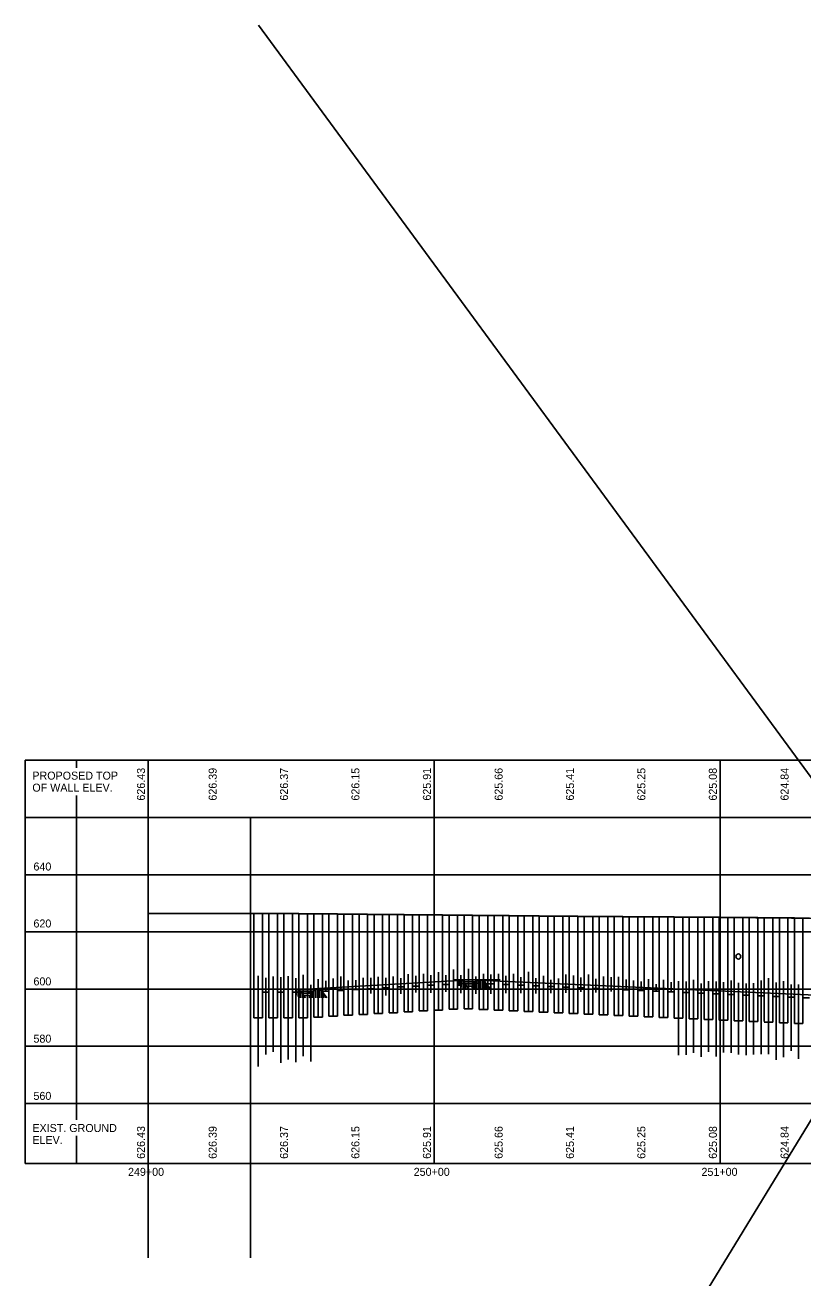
# Model space of a CAD drawing. Extents: x 2267596 to 2268160, y 712626 to 714793.
# Drawn here: x 2267595.7 to 2267867.7, y 712887.4 to 713325.6 of the extents above; entities that cross this region are included whole.
import ezdxf

# ---------------------------------------------------------------- set-up
doc = ezdxf.new("R2010")
doc.units = 0
for name, color, linetype in [('BR_P_Gen_Text', 7, 'Continuous'), ('BR_P_Sub_Deep_Object', 7, 'Continuous'), ('Default', 7, 'Continuous'), ('DR_X_Storm_Sewer', 7, 'Continuous'), ('GE_X_Alignment', 7, 'Continuous'), ('SC_Scratch1', 7, 'Continuous'), ('SC_Scratch9', 7, 'Continuous'), ('SH_Major_Grid_Line', 7, 'Continuous'), ('XS_X_Ground_Line', 7, 'Continuous')]:
    doc.layers.add(name, color=color, linetype=linetype)

msp = doc.modelspace()

# ---------------------------------------------------------------- linework, layer by layer
at = {"layer": 'BR_P_Sub_Deep_Object'}
for p, q in [((2267675.74, 713014.81), (2267675.74, 712978.33)), ((2267675.74, 713014.81), (2267678.74, 713014.81)), ((2267678.74, 713014.81), (2267678.74, 712978.33)), ((2267678.74, 713014.81), (2267680.99, 713014.81)), ((2267680.99, 713014.81), (2267680.99, 712978.33)), ((2267680.99, 713014.81), (2267683.99, 713014.8)), ((2267683.99, 713014.8), (2267683.99, 712978.33)), ((2267683.99, 713014.8), (2267686.24, 713014.8)), ((2267686.24, 713014.8), (2267686.24, 712978.33)), ((2267686.24, 713014.8), (2267689.24, 713014.8)), ((2267689.24, 713014.8), (2267689.24, 712978.33)), ((2267689.24, 713014.8), (2267691.49, 713014.8)), ((2267691.49, 713014.8), (2267691.49, 712978.34)), ((2267691.49, 713014.78), (2267694.49, 713014.78)), ((2267694.49, 713014.78), (2267694.49, 712978.34)), ((2267694.49, 713014.75), (2267696.74, 713014.75)), ((2267696.74, 713014.75), (2267696.74, 712978.64)), ((2267696.74, 713014.73), (2267699.74, 713014.73)), ((2267699.74, 713014.73), (2267699.74, 712978.64)), ((2267699.74, 713014.7), (2267701.99, 713014.7)), ((2267701.99, 713014.7), (2267701.99, 712978.94)), ((2267701.99, 713014.68), (2267704.99, 713014.68)), ((2267704.99, 713014.68), (2267704.99, 712978.94)), ((2267704.99, 713014.66), (2267707.24, 713014.66)), ((2267707.24, 713014.66), (2267707.24, 712979.25)), ((2267707.24, 713014.64), (2267710.24, 713014.64)), ((2267710.24, 713014.64), (2267710.24, 712979.25)), ((2267710.24, 713014.61), (2267712.49, 713014.61)), ((2267712.49, 713014.61), (2267712.49, 712979.55)), ((2267712.49, 713014.59), (2267715.49, 713014.59)), ((2267715.49, 713014.59), (2267715.49, 712979.55)), ((2267715.49, 713014.56), (2267717.74, 713014.56)), ((2267717.74, 713014.56), (2267717.74, 712979.86)), ((2267717.74, 713014.54), (2267720.74, 713014.54)), ((2267720.74, 713014.54), (2267720.74, 712979.86)), ((2267720.74, 713014.51), (2267722.99, 713014.51)), ((2267722.99, 713014.51), (2267722.99, 712980.16)), ((2267722.99, 713014.49), (2267725.99, 713014.49)), ((2267725.99, 713014.49), (2267725.99, 712980.16)), ((2267725.99, 713014.46), (2267728.24, 713014.46)), ((2267728.24, 713014.46), (2267728.24, 712980.47)), ((2267728.24, 713014.44), (2267731.24, 713014.44)), ((2267731.24, 713014.44), (2267731.24, 712980.47)), ((2267731.24, 713014.41), (2267733.49, 713014.41)), ((2267733.49, 713014.41), (2267733.49, 712980.77)), ((2267733.49, 713014.39), (2267736.49, 713014.39)), ((2267736.49, 713014.39), (2267736.49, 712980.77)), ((2267736.49, 713014.36), (2267738.74, 713014.36)), ((2267738.74, 712981.07), (2267738.74, 713014.36)), ((2267738.74, 713014.34), (2267741.74, 713014.34)), ((2267741.74, 713014.34), (2267741.74, 712981.07)), ((2267741.74, 713014.31), (2267743.99, 713014.31)), ((2267743.99, 713014.31), (2267743.99, 712981.38)), ((2267743.99, 713014.29), (2267746.99, 713014.29)), ((2267746.99, 713014.29), (2267746.99, 712981.38)), ((2267746.99, 713014.26), (2267749.24, 713014.26)), ((2267749.24, 713014.26), (2267749.24, 712981.49)), ((2267749.24, 713014.23), (2267752.24, 713014.23)), ((2267752.24, 713014.23), (2267752.24, 712981.49)), ((2267752.24, 713014.2), (2267754.49, 713014.2)), ((2267754.49, 713014.2), (2267754.49, 712981.25)), ((2267754.49, 713014.18), (2267757.49, 713014.18)), ((2267757.49, 713014.18), (2267757.49, 712981.25)), ((2267757.49, 713014.15), (2267759.74, 713014.15)), ((2267759.74, 713014.15), (2267759.74, 712981.02)), ((2267759.74, 713014.13), (2267762.74, 713014.13)), ((2267762.74, 713014.13), (2267762.74, 712981.02)), ((2267762.74, 713014.1), (2267764.99, 713014.1)), ((2267764.99, 713014.1), (2267764.99, 712980.79)), ((2267764.99, 713014.08), (2267767.99, 713014.08)), ((2267767.99, 713014.08), (2267767.99, 712980.79)), ((2267767.99, 713014.05), (2267770.24, 713014.05)), ((2267770.24, 713014.05), (2267770.24, 712980.55)), ((2267770.24, 713014.02), (2267773.24, 713014.02)), ((2267773.24, 713014.02), (2267773.24, 712980.55)), ((2267773.24, 713013.99), (2267775.49, 713013.99)), ((2267775.49, 713013.99), (2267775.49, 712980.32)), ((2267775.49, 713013.97), (2267778.49, 713013.97)), ((2267778.49, 713013.97), (2267778.49, 712980.32)), ((2267778.49, 713013.94), (2267780.74, 713013.94)), ((2267780.74, 713013.94), (2267780.74, 712980.08)), ((2267780.74, 713013.92), (2267783.74, 713013.92)), ((2267783.74, 713013.92), (2267783.74, 712980.08)), ((2267783.74, 713013.89), (2267785.99, 713013.89)), ((2267785.99, 713013.89), (2267785.99, 712979.85)), ((2267785.99, 713013.87), (2267788.99, 713013.87)), ((2267788.99, 713013.87), (2267788.99, 712979.85)), ((2267788.99, 713013.84), (2267791.24, 713013.84)), ((2267791.24, 713013.84), (2267791.24, 712979.62)), ((2267791.24, 713013.82), (2267794.24, 713013.82)), ((2267794.24, 713013.82), (2267794.24, 712979.62)), ((2267794.24, 713013.8), (2267796.49, 713013.8)), ((2267796.49, 713013.8), (2267796.49, 712979.38)), ((2267796.49, 713013.79), (2267799.49, 713013.79)), ((2267799.49, 713013.79), (2267799.49, 712979.38)), ((2267799.49, 713013.77), (2267801.74, 713013.77)), ((2267801.74, 713013.77), (2267801.74, 712979.15)), ((2267801.74, 713013.76), (2267804.74, 713013.76)), ((2267804.74, 713013.76), (2267804.74, 712979.15)), ((2267804.74, 713013.74), (2267806.99, 713013.74)), ((2267806.99, 713013.74), (2267806.99, 712978.91)), ((2267806.99, 713013.72), (2267809.99, 713013.72)), ((2267809.99, 713013.72), (2267809.99, 712978.91)), ((2267809.99, 713013.7), (2267812.24, 713013.7)), ((2267812.24, 713013.7), (2267812.24, 712978.68)), ((2267812.24, 713013.69), (2267815.24, 713013.69)), ((2267815.24, 713013.69), (2267815.24, 712978.68)), ((2267815.24, 713013.67), (2267817.49, 713013.67)), ((2267817.49, 713013.67), (2267817.49, 712978.45)), ((2267817.49, 713013.65), (2267820.49, 713013.65)), ((2267820.49, 713013.65), (2267820.49, 712978.45)), ((2267820.49, 713013.63), (2267822.74, 713013.63)), ((2267822.74, 713013.63), (2267822.74, 712978.21)), ((2267822.74, 713013.62), (2267825.74, 713013.62)), ((2267825.74, 713013.62), (2267825.74, 712978.21)), ((2267825.74, 713013.6), (2267827.99, 713013.6)), ((2267827.99, 713013.6), (2267827.99, 712977.98)), ((2267827.99, 713013.58), (2267830.99, 713013.58)), ((2267830.99, 713013.58), (2267830.99, 712977.98)), ((2267830.99, 713013.56), (2267833.24, 713013.56)), ((2267833.24, 713013.56), (2267833.24, 712977.75)), ((2267833.24, 713013.55), (2267836.24, 713013.55)), ((2267836.24, 713013.55), (2267836.24, 712977.75)), ((2267836.24, 713013.53), (2267838.49, 713013.53)), ((2267838.49, 713013.53), (2267838.49, 712977.51)), ((2267838.49, 713013.51), (2267841.49, 713013.51)), ((2267841.49, 713013.51), (2267841.49, 712977.51)), ((2267841.49, 713013.48), (2267843.74, 713013.48)), ((2267843.74, 713013.48), (2267843.74, 712977.28)), ((2267843.74, 713013.46), (2267846.74, 713013.46)), ((2267846.74, 713013.46), (2267846.74, 712977.28)), ((2267846.74, 713013.43), (2267848.99, 713013.43)), ((2267848.99, 713013.43), (2267848.99, 712977.04)), ((2267848.99, 713013.41), (2267851.99, 713013.41)), ((2267851.99, 713013.41), (2267851.99, 712977.04)), ((2267851.99, 713013.38), (2267854.24, 713013.38)), ((2267854.24, 713013.38), (2267854.24, 712977.04)), ((2267854.24, 713013.36), (2267857.24, 713013.36)), ((2267857.24, 713013.36), (2267857.24, 712976.81)), ((2267857.24, 713013.33), (2267859.49, 713013.33)), ((2267859.49, 713013.33), (2267859.49, 712976.58)), ((2267859.49, 713013.31), (2267862.49, 713013.31)), ((2267862.49, 713013.31), (2267862.49, 712976.58)), ((2267862.49, 713013.28), (2267864.74, 713013.28)), ((2267864.74, 713013.28), (2267864.74, 712976.34)), ((2267864.74, 713013.26), (2267867.74, 713013.26)), ((2267867.74, 713013.26), (2267867.74, 712976.34)), ((2267867.74, 713013.25), (2267869.99, 713013.25)), ((2267731.24, 712989.47), (2267733.49, 712989.47)), ((2267736.49, 712989.77), (2267738.74, 712989.77)), ((2267741.74, 712990.07), (2267743.99, 712990.07)), ((2267746.99, 712990.38), (2267749.24, 712990.38)), ((2267754.49, 712990.49), (2267752.24, 712990.49)), ((2267759.74, 712990.25), (2267757.49, 712990.25)), ((2267764.99, 712990.02), (2267762.74, 712990.02)), ((2267770.24, 712989.79), (2267767.99, 712989.79)), ((2267775.49, 712989.55), (2267773.24, 712989.55)), ((2267780.74, 712989.32), (2267778.49, 712989.32)), ((2267678.74, 712987.33), (2267680.99, 712987.33)), ((2267683.99, 712987.33), (2267686.24, 712987.33)), ((2267689.24, 712987.33), (2267691.49, 712987.33)), ((2267694.49, 712987.34), (2267696.74, 712987.34)), ((2267699.74, 712987.64), (2267701.99, 712987.64)), ((2267704.99, 712987.94), (2267707.24, 712987.94)), ((2267710.24, 712988.25), (2267712.49, 712988.25)), ((2267715.49, 712988.55), (2267717.74, 712988.55)), ((2267720.74, 712988.86), (2267722.99, 712988.86)), ((2267725.99, 712989.16), (2267728.24, 712989.16)), ((2267785.99, 712989.08), (2267783.74, 712989.08)), ((2267791.24, 712988.85), (2267788.99, 712988.85)), ((2267796.49, 712988.62), (2267794.24, 712988.62)), ((2267801.74, 712988.38), (2267799.49, 712988.38)), ((2267806.99, 712988.15), (2267804.74, 712988.15)), ((2267812.24, 712987.91), (2267809.99, 712987.91)), ((2267817.49, 712987.68), (2267815.24, 712987.68)), ((2267822.74, 712987.45), (2267820.49, 712987.45)), ((2267827.99, 712987.21), (2267825.74, 712987.21)), ((2267833.24, 712986.98), (2267830.99, 712986.98)), ((2267838.49, 712986.75), (2267836.24, 712986.75)), ((2267843.74, 712986.51), (2267841.49, 712986.51)), ((2267848.99, 712986.28), (2267846.74, 712986.28)), ((2267854.24, 712986.04), (2267851.99, 712986.04)), ((2267859.49, 712985.81), (2267857.24, 712985.81)), ((2267864.74, 712985.58), (2267862.49, 712985.58)), ((2267869.99, 712985.34), (2267867.74, 712985.34)), ((2267733.49, 712980.77), (2267736.49, 712980.77)), ((2267738.74, 712981.07), (2267741.74, 712981.07)), ((2267743.99, 712981.38), (2267746.99, 712981.38)), ((2267752.24, 712981.49), (2267749.24, 712981.49)), ((2267757.49, 712981.25), (2267754.49, 712981.25)), ((2267762.74, 712981.02), (2267759.74, 712981.02)), ((2267767.99, 712980.79), (2267764.99, 712980.79)), ((2267773.24, 712980.55), (2267770.24, 712980.55)), ((2267675.74, 712978.33), (2267678.74, 712978.33)), ((2267680.99, 712978.33), (2267683.99, 712978.33)), ((2267686.24, 712978.33), (2267689.24, 712978.33)), ((2267691.49, 712978.34), (2267694.49, 712978.34)), ((2267696.74, 712978.64), (2267699.74, 712978.64)), ((2267701.99, 712978.94), (2267704.99, 712978.94)), ((2267707.24, 712979.25), (2267710.24, 712979.25)), ((2267712.49, 712979.55), (2267715.49, 712979.55)), ((2267717.74, 712979.86), (2267720.74, 712979.86)), ((2267722.99, 712980.16), (2267725.99, 712980.16)), ((2267728.24, 712980.47), (2267731.24, 712980.47)), ((2267778.49, 712980.32), (2267775.49, 712980.32)), ((2267783.74, 712980.08), (2267780.74, 712980.08)), ((2267788.99, 712979.85), (2267785.99, 712979.85)), ((2267794.24, 712979.62), (2267791.24, 712979.62)), ((2267799.49, 712979.38), (2267796.49, 712979.38)), ((2267804.74, 712979.15), (2267801.74, 712979.15)), ((2267809.99, 712978.91), (2267806.99, 712978.91)), ((2267815.24, 712978.68), (2267812.24, 712978.68)), ((2267820.49, 712978.45), (2267817.49, 712978.45)), ((2267825.74, 712978.21), (2267822.74, 712978.21)), ((2267830.99, 712977.98), (2267827.99, 712977.98)), ((2267836.24, 712977.75), (2267833.24, 712977.75)), ((2267841.49, 712977.51), (2267838.49, 712977.51)), ((2267846.74, 712977.28), (2267843.74, 712977.28)), ((2267851.99, 712977.04), (2267848.99, 712977.04)), ((2267857.24, 712976.81), (2267854.24, 712976.81)), ((2267862.49, 712976.58), (2267859.49, 712976.58)), ((2267867.74, 712976.34), (2267864.74, 712976.34))]:
    msp.add_line(p, q, dxfattribs=at)
at = {"layer": 'Default'}
for p, q in [((2267761.9, 712991.63), (2267745.5, 712991.63)), ((2267747.52, 712991.63), (2267747.52, 712989.57)), ((2267748.21, 712991.63), (2267748.21, 712989.14)), ((2267748.43, 712991.63), (2267750.7, 712988.68)), ((2267748.9, 712991.02), (2267748.9, 712988.68)), ((2267753.67, 712990.99), (2267748.9, 712990.99)), ((2267753.12, 712990.23), (2267749.51, 712990.23)), ((2267749.59, 712990.12), (2267749.59, 712988.68)), ((2267752.55, 712989.44), (2267750.11, 712989.44)), ((2267754.14, 712991.63), (2267752, 712988.68)), ((2267753.02, 712990.09), (2267753.02, 712988.68)), ((2267753.67, 712990.99), (2267753.67, 712988.68)), ((2267754.36, 712991.63), (2267754.36, 712988.68)), ((2267755.05, 712991.63), (2267755.05, 712988.68)), ((2267755.75, 712991.63), (2267755.75, 712988.68)), ((2267755.96, 712991.63), (2267758.24, 712988.68)), ((2267756.44, 712991.02), (2267756.44, 712988.68)), ((2267757.13, 712990.12), (2267757.13, 712988.68)), ((2267704.94, 712988.33), (2267688.55, 712988.33)), ((2267690.56, 712988.33), (2267690.56, 712986.27)), ((2267691.26, 712988.33), (2267691.26, 712985.84)), ((2267691.47, 712988.33), (2267693.75, 712985.38)), ((2267691.95, 712987.72), (2267691.95, 712985.38)), ((2267696.72, 712987.69), (2267691.95, 712987.69)), ((2267696.17, 712986.93), (2267692.55, 712986.93)), ((2267692.64, 712986.82), (2267692.64, 712985.38)), ((2267695.6, 712986.14), (2267693.16, 712986.14)), ((2267693.32, 712985.93), (2267693.32, 712985.38)), ((2267697.18, 712988.33), (2267695.05, 712985.38)), ((2267695.41, 712985.88), (2267695.41, 712985.38)), ((2267696.07, 712986.79), (2267696.07, 712985.38)), ((2267696.72, 712987.69), (2267696.72, 712985.38)), ((2267697.41, 712988.33), (2267697.41, 712985.38)), ((2267698.1, 712988.33), (2267698.1, 712985.38)), ((2267698.79, 712988.33), (2267698.79, 712985.38)), ((2267699.01, 712988.33), (2267701.29, 712985.38)), ((2267699.48, 712987.72), (2267699.48, 712985.38)), ((2267700.17, 712986.82), (2267700.17, 712985.38)), ((2267700.86, 712985.93), (2267700.86, 712985.38)), ((2267750.27, 712989.23), (2267750.27, 712988.68)), ((2267752.37, 712989.18), (2267752.37, 712988.68)), ((2267757.81, 712989.23), (2267757.81, 712988.68))]:
    msp.add_line(p, q, dxfattribs=at)
at = {"layer": 'DR_X_Storm_Sewer'}
msp.add_circle((2267845.16, 712999.81), 0.876, dxfattribs=at)
at = {"layer": 'GE_X_Alignment'}
for p, q in [((2267613.74, 713065.77), (2267613.74, 713068.43)), ((2267638.74, 712927.44), (2267638.74, 713068.43)), ((2267738.74, 712927.44), (2267738.74, 713068.43)), ((2267838.74, 712927.44), (2267838.74, 713068.43)), ((2267613.74, 712942.64), (2267613.74, 713056.13)), ((2267595.7, 713048.43), (2268156.77, 713048.43)), ((2267595.7, 713028.43), (2268156.77, 713028.43)), ((2267595.7, 713008.43), (2268156.77, 713008.43)), ((2267595.7, 712988.43), (2268156.77, 712988.43)), ((2267595.7, 712968.43), (2268156.77, 712968.43)), ((2267595.7, 712948.43), (2268156.77, 712948.43)), ((2267613.74, 712927.44), (2267613.74, 712937.13))]:
    msp.add_line(p, q, dxfattribs=at)
at = {"layer": 'SC_Scratch1'}
for p, q in [((2267677.34, 713325.63), (2268155.15, 712674.91)), ((2267677.34, 712625.8), (2268081.64, 713288.8)), ((2267638.74, 713048.43), (2267638.74, 712894.37)), ((2267674.53, 713048.43), (2267674.53, 712894.37)), ((2267734.99, 712980.77), (2267734.99, 712993.7)), ((2267740.24, 712981.07), (2267740.24, 712994.28)), ((2267745.49, 712981.38), (2267745.49, 712995.28)), ((2267750.74, 712981.49), (2267750.74, 712995.51)), ((2267755.99, 712981.25), (2267755.99, 712993.79)), ((2267761.24, 712981.02), (2267761.24, 712993.76)), ((2267766.49, 712980.79), (2267766.49, 712993.73)), ((2267771.74, 712980.55), (2267771.74, 712994.47)), ((2267677.24, 712961.37), (2267677.24, 712993.07)), ((2267679.87, 712965.5), (2267679.87, 712992.29)), ((2267682.49, 712966.45), (2267682.49, 712992.76)), ((2267685.12, 712962.66), (2267685.12, 712992.6)), ((2267687.74, 712963.74), (2267687.74, 712992.92)), ((2267690.37, 712962.87), (2267690.37, 712992.18)), ((2267692.99, 712964.9), (2267692.99, 712993.38)), ((2267695.62, 712963.08), (2267695.62, 712989.88)), ((2267698.24, 712978.64), (2267698.24, 712991.84)), ((2267700.87, 712987.64), (2267700.87, 712991.33)), ((2267703.49, 712978.94), (2267703.49, 712992.17)), ((2267706.12, 712987.94), (2267706.12, 712992.83)), ((2267708.74, 712979.25), (2267708.74, 712991.45)), ((2267711.37, 712988.25), (2267711.37, 712991.56)), ((2267713.99, 712979.55), (2267713.99, 712992.34)), ((2267716.62, 712986.89), (2267716.62, 712992.34)), ((2267719.24, 712979.86), (2267719.24, 712992.71)), ((2267721.87, 712986.18), (2267721.87, 712992.29)), ((2267724.49, 712980.16), (2267724.49, 712992.76)), ((2267727.12, 712986.75), (2267727.12, 712992.18)), ((2267729.74, 712980.47), (2267729.74, 712993.65)), ((2267732.37, 712987.17), (2267732.37, 712993.07)), ((2267737.62, 712987.08), (2267737.62, 712993.23)), ((2267742.87, 712987.5), (2267742.87, 712993.33)), ((2267748.12, 712986.94), (2267748.12, 712993.33)), ((2267753.37, 712986.76), (2267753.37, 712992.84)), ((2267758.62, 712986.7), (2267758.62, 712993.47)), ((2267763.87, 712987.04), (2267763.87, 712993)), ((2267769.12, 712987.04), (2267769.12, 712992.53)), ((2267774.37, 712986.83), (2267774.37, 712992.27)), ((2267776.99, 712980.32), (2267776.99, 712993)), ((2267779.62, 712986.94), (2267779.62, 712991.69)), ((2267782.24, 712980.08), (2267782.24, 712992.15)), ((2267784.87, 712987.07), (2267784.87, 712993.56)), ((2267787.49, 712979.85), (2267787.49, 712993.15)), ((2267790.12, 712987.43), (2267790.12, 712992.52)), ((2267792.74, 712979.62), (2267792.74, 712993.46)), ((2267795.37, 712987.27), (2267795.37, 712991.99)), ((2267797.99, 712979.38), (2267797.99, 712992.83)), ((2267800.62, 712987.53), (2267800.62, 712992.59)), ((2267803.24, 712979.15), (2267803.24, 712992.68)), ((2267805.87, 712988.15), (2267805.87, 712991.72)), ((2267808.49, 712978.91), (2267808.49, 712991.39)), ((2267811.12, 712987.91), (2267811.12, 712991.06)), ((2267813.74, 712978.68), (2267813.74, 712991.84)), ((2267816.37, 712987.68), (2267816.37, 712990.14)), ((2267818.99, 712978.45), (2267818.99, 712991.64)), ((2267821.62, 712987.45), (2267821.62, 712990.85)), ((2267824.24, 712965.26), (2267824.24, 712991.17)), ((2267826.87, 712965.44), (2267826.87, 712991.01)), ((2267829.49, 712966.17), (2267829.49, 712991.69)), ((2267832.12, 712964.67), (2267832.12, 712990.33)), ((2267834.74, 712966.41), (2267834.74, 712991.22)), ((2267837.37, 712964.86), (2267837.37, 712991.06)), ((2267839.99, 712966.23), (2267839.99, 712990.85)), ((2267842.62, 712966.17), (2267842.62, 712991.41)), ((2267845.24, 712965.53), (2267845.24, 712990.64)), ((2267847.87, 712965.29), (2267847.87, 712990.37)), ((2267850.49, 712965.56), (2267850.49, 712990.49)), ((2267853.12, 712965.61), (2267853.12, 712991.4)), ((2267855.74, 712965.61), (2267855.74, 712992.23)), ((2267858.37, 712963.68), (2267858.37, 712990.76)), ((2267860.99, 712964.64), (2267860.99, 712991.22)), ((2267863.62, 712966.79), (2267863.62, 712990)), ((2267866.24, 712964.01), (2267866.24, 712989.97))]:
    msp.add_line(p, q, dxfattribs=at)
at = {"layer": 'SC_Scratch9'}
for p, q in [((2267751.31, 712991.41), (2267751.31, 712991.93)), ((2267694.36, 712988.11), (2267694.36, 712988.63))]:
    msp.add_line(p, q, dxfattribs=at)
at = {"layer": 'SH_Major_Grid_Line'}
for p, q in [((2267595.7, 712927.44), (2267595.7, 713068.43)), ((2268156.77, 713068.43), (2267595.7, 713068.43)), ((2268156.77, 712927.44), (2267595.7, 712927.44))]:
    msp.add_line(p, q, dxfattribs=at)
at = {"layer": 'XS_X_Ground_Line'}
msp.add_line((2267694.36, 712988.33), (2267671.93, 712988.33), dxfattribs=at)
for points in [[(2267638.74, 713014.86), (2267663.74, 713014.82), (2267688.74, 713014.8), (2267713.74, 713014.58), (2267738.74, 713014.34), (2267788.74, 713013.84), (2267813.74, 713013.68), (2267838.74, 713013.51), (2267863.74, 713013.27), (2267888.74, 713013.12), (2267913.74, 713012.95), (2267938.74, 713012.75), (2267963.74, 713012.81), (2267988.74, 713012.74), (2268013.74, 713012.53), (2268049.99, 713012.3)], [(2267694.36, 712988.33), (2267751.31, 712991.63), (2267874.79, 712986.13), (2267952.95, 712990.53), (2268025.6, 712987.03)]]:
    msp.add_lwpolyline(points, dxfattribs=at)

# ---------------------------------------------------------------- texts
at = {"layer": 'BR_P_Gen_Text'}
for s, p in [('PROPOSED TOP ', (2267598.26, 713061.68)), ('OF WALL ELEV.', (2267598.26, 713057.48)), ('640', (2267598.64, 713029.89)), ('620', (2267598.64, 713009.96)), ('600', (2267598.64, 712989.7)), ('580', (2267598.64, 712969.67)), ('560', (2267598.64, 712949.65)), ('EXIST. GROUND', (2267598.26, 712938.41)), ('ELEV.', (2267598.26, 712934.21)), ('249+00', (2267631.71, 712923.08)), ('250+00', (2267731.62, 712923.08)), ('251+00', (2267832.27, 712923.08))]:
    msp.add_text(s, height=2.8, dxfattribs=at).set_placement(p)
for s, p in [('626.43', (2267637.64, 713054.34)), ('626.39', (2267662.72, 713054.34)), ('626.37', (2267687.66, 713054.34)), ('626.15', (2267712.63, 713054.34)), ('625.91', (2267737.64, 713054.34)), ('625.66', (2267762.72, 713054.34)), ('625.41', (2267787.66, 713054.34)), ('625.25', (2267812.63, 713054.34)), ('625.08', (2267837.64, 713054.34)), ('624.84', (2267862.72, 713054.34)), ('626.43', (2267637.64, 712929.04)), ('626.39', (2267662.72, 712929.04)), ('626.37', (2267687.66, 712929.04)), ('626.15', (2267712.63, 712929.04)), ('625.91', (2267737.64, 712929.04)), ('625.66', (2267762.72, 712929.04)), ('625.41', (2267787.66, 712929.04)), ('625.25', (2267812.63, 712929.04)), ('625.08', (2267837.64, 712929.04)), ('624.84', (2267862.72, 712929.04))]:
    msp.add_text(s, height=2.8, rotation=90, dxfattribs=at).set_placement(p)

doc.saveas('drawing.dxf')
